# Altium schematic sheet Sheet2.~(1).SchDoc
size A3
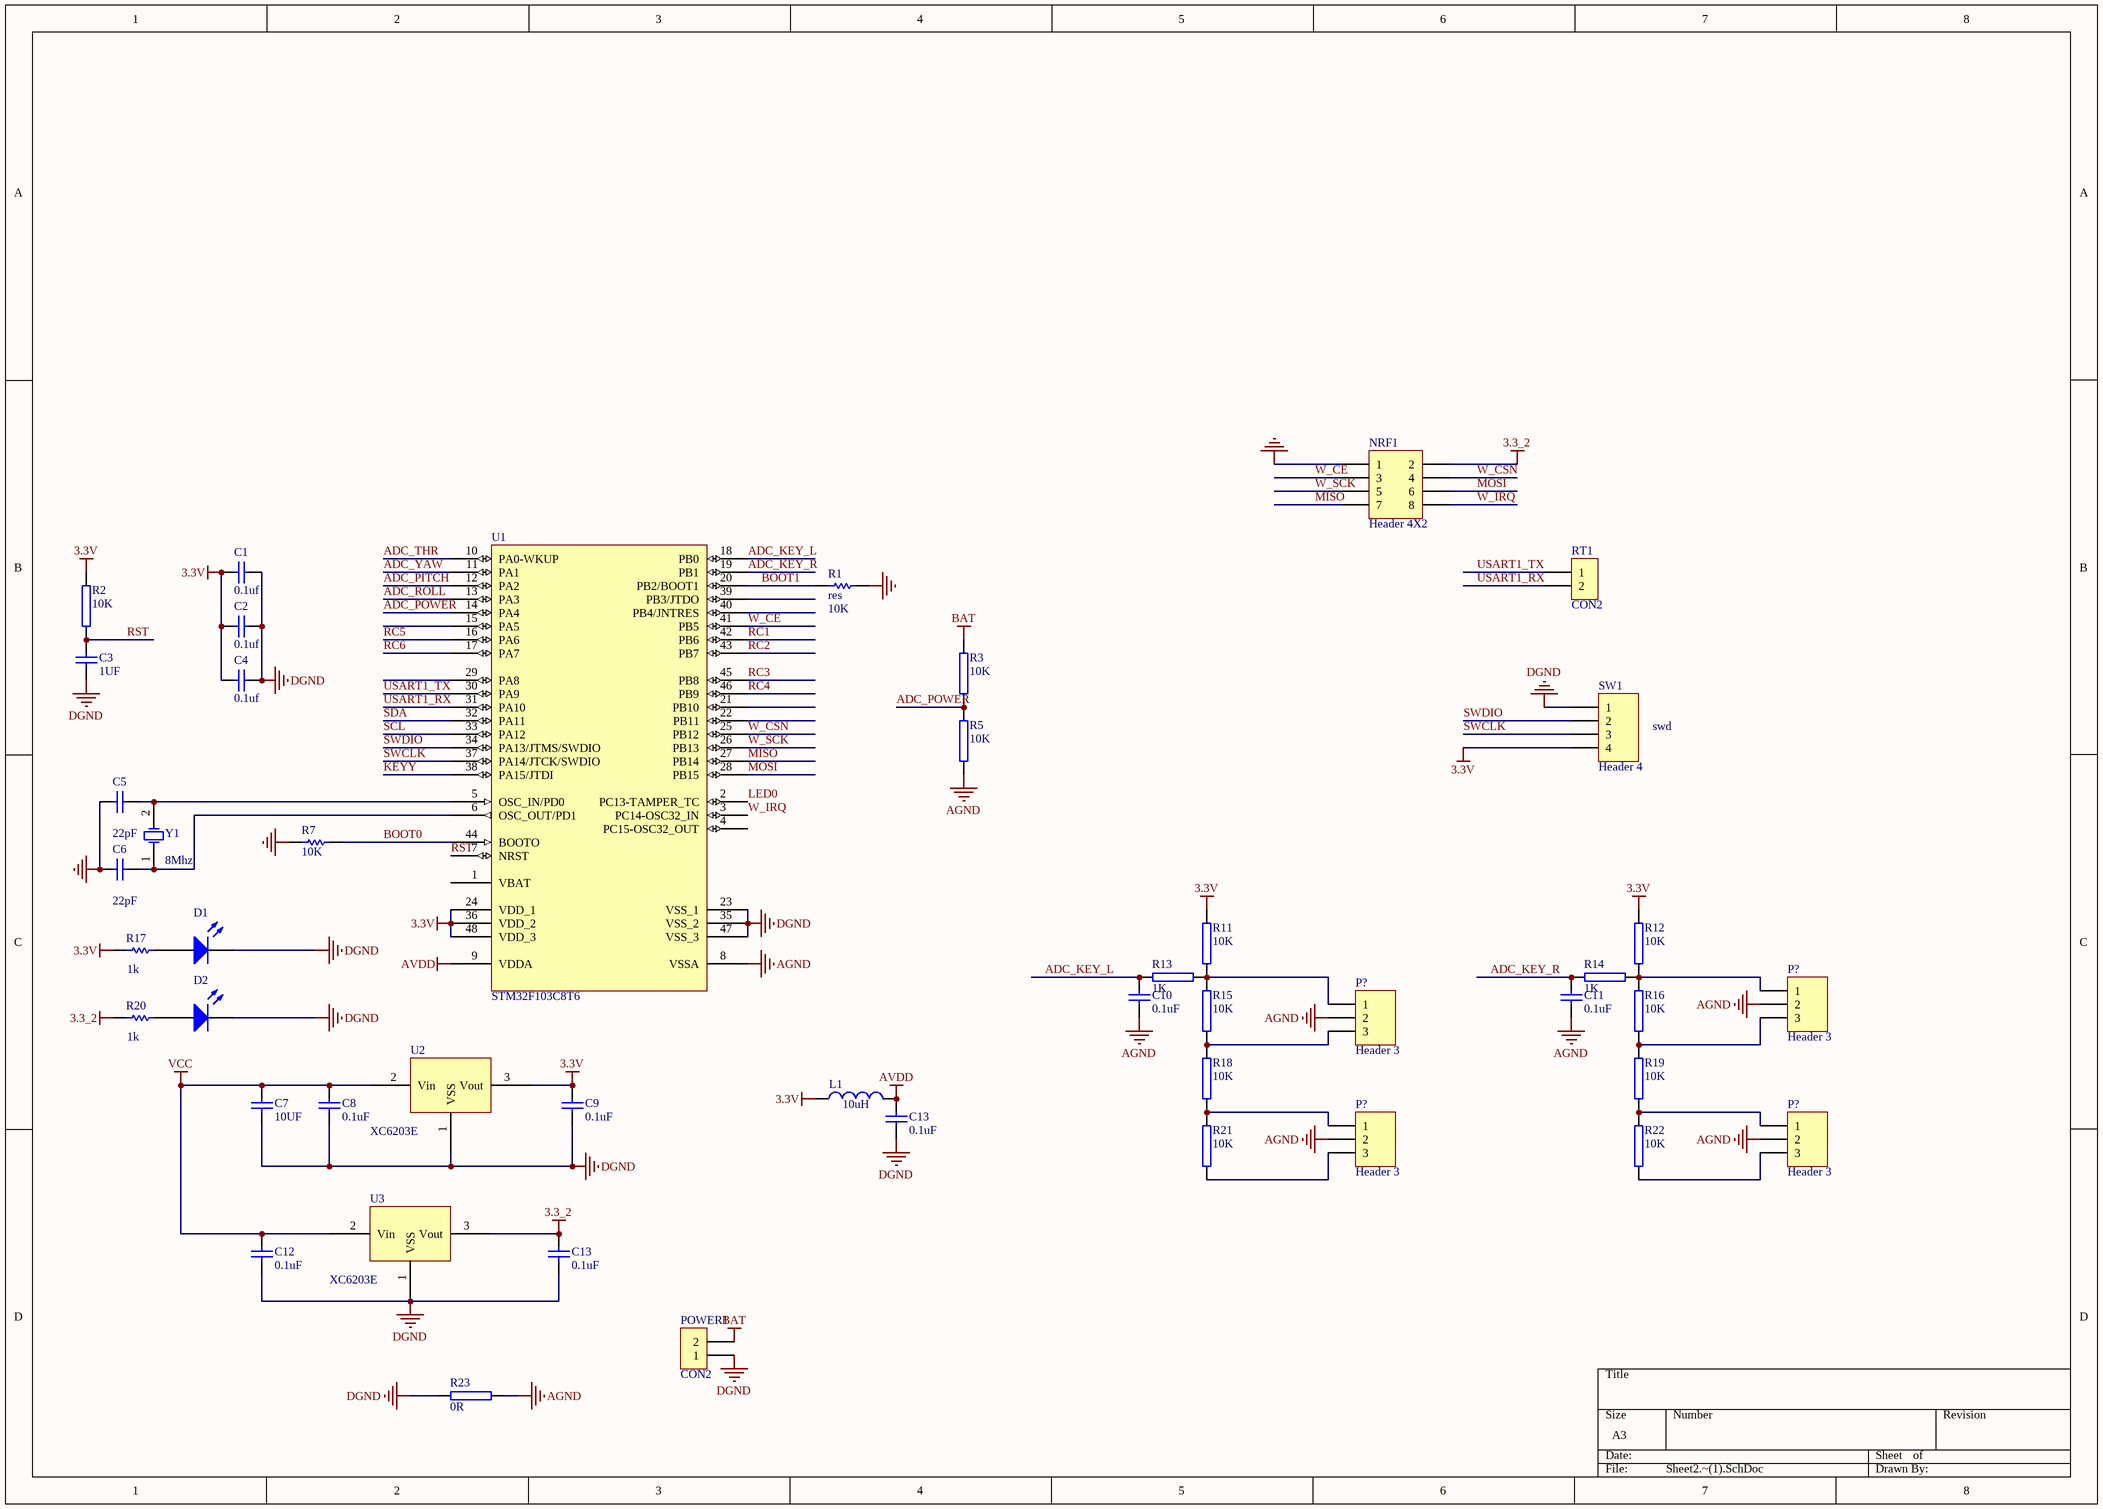
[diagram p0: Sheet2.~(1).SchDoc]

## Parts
(Parts that share a designator on the sheet are numbered #1, #2 ... from top to bottom, then left to right.)
C1  value 0.1uf  [0805]  (hidden comment: cap)
C2  value 0.1uf  [0805]  (hidden comment: cap)
C3  value 1UF  [0805]  (hidden comment: cap)
C4  value 0.1uf  [0805]  (hidden comment: cap)
C5  value 22pF  [0805]  (hidden comment: cap)
C6  value 22pF  [0805]  (hidden comment: cap)
C7  value 10UF  [0805]  (hidden comment: cap)
C8  value 0.1uF  [0805]  (hidden comment: cap)
C9  value 0.1uF  [0805]  (hidden comment: cap)
C10  value 0.1uF  [0805]  (hidden comment: cap)
C11  value 0.1uF  [0805]  (hidden comment: cap)
C12  value 0.1uF  [0805]  (hidden comment: cap)
C13#1  value 0.1uF  [0805]  (hidden comment: cap)
C13#2  value 0.1uF  [0805]  (hidden comment: cap)
D1  LED0  [0805]  (value not drawn)
D2  LED0  [0805]  (value not drawn)
L1  value 10uH  [0805]  (hidden comment: Inductor)
NRF1  Header 4X2  [HDR2X4]
P?#1  Header 3  [HDR1X3]
P?#2  Header 3  [HDR1X3]
P?#3  Header 3  [HDR1X3]
P?#4  Header 3  [HDR1X3]
POWER1  CON2  [SIP2]
R1  res  res: 10K  [0805]
R2  10K  [0805]
R3  10K  [0805]
R5  10K  [0805]
R7  res: 10K  [0805]  (hidden comment: res)
R11  10K  [0805]
R12  10K  [0805]
R13  1K  [0805]
R14  1K  [0805]
R15  10K  [0805]
R16  10K  [0805]
R17  res: 1k  [0805]  (hidden comment: res)
R18  10K  [0805]
R19  10K  [0805]
R20  res: 1k  [0805]  (hidden comment: res)
R21  10K  [0805]
R22  10K  [0805]
R23  0R  [0805]
RT1  CON2  [SIP2]
SW1  Header 4  [HDR1X4]
U1  STM32F103C8T6  [LQFP48S]
U2  XC6203E  [SOT-89]
U3  XC6203E  [SOT-89]
Y1  5032xtal  [XTAL]  (value not drawn)

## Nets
3.3_2: C13#2.2 NRF1.2 R20.1 U3.3(Vout)
3.3V: C1.2 C2.2 C4.2 C9.2 L1.1 R2.2 R11.2 R12.2 R17.1 SW1.4 U1.24(VDD_1) U1.36(VDD_2) U1.48(VDD_3) U2.3(Vout)
AGND: C10.1 C11.1 P?#1.2 P?#2.2 P?#3.2 P?#4.2 R5.1 R23.2 U1.8(VSSA)
AVDD: C13#1.2 L1.2 U1.9(VDDA)
BAT: POWER1.2 R3.2
DGND: C1.1 C2.1 C3.1 C4.1 C7.1 C8.1 C9.1 C12.1 C13#1.1 C13#2.1 D1.2(K) D2.2(K) POWER1.1 R23.1 SW1.1 U1.23(VSS_1) U1.35(VSS_2) U1.47(VSS_3) U2.1(VSS) U3.1(VSS)
GND: C5.1 C6.1 NRF1.1 R1.2 R7.1
VCC: C7.2 C8.2 C12.2 U2.2(Vin) U3.2(Vin)
ADC_KEY_L: C10.2 R13.2 U1.18(PB0)
ADC_KEY_R: C11.2 R14.2 U1.19(PB1)
ADC_PITCH: U1.12(PA2)
ADC_POWER: R3.1 R5.2 U1.14(PA4)
ADC_ROLL: U1.13(PA3)
ADC_THR: U1.10(PA0-WKUP)
ADC_YAW: U1.11(PA1)
BOOT0: R7.2 U1.44(BOOTO)
BOOT1: R1.1 U1.20(PB2/BOOT1)
KEYY: U1.38(PA15/JTDI)
LED0: U1.2(PC13-TAMPER_TC)
MISO: NRF1.7 U1.27(PB14)
MOSI: NRF1.6 U1.28(PB15)
RC1: U1.42(PB6)
RC2: U1.43(PB7)
RC3: U1.45(PB8)
RC4: U1.46(PB9)
RC5: U1.16(PA6)
RC6: U1.17(PA7)
RST: C3.2 R2.1 U1.7(NRST)
SCL: U1.33(PA12)
SDA: U1.32(PA11)
SWCLK: SW1.3 U1.37(PA14/JTCK/SWDIO)
SWDIO: SW1.2 U1.34(PA13/JTMS/SWDIO)
USART1_RX: RT1.2 U1.31(PA10)
USART1_TX: RT1.1 U1.30(PA9)
W_CE: NRF1.3 U1.41(PB5)
W_CSN: NRF1.4 U1.25(PB12)
W_IRQ: NRF1.8 U1.3(PC14-OSC32_IN)
W_SCK: NRF1.5 U1.26(PB13)
NetC5_2: C5.2 U1.5(OSC_IN/PD0) Y1.2(OSC2)
NetC6_2: C6.2 U1.6(OSC_OUT/PD1) Y1.1(OSC1)
NetD1_1: D1.1(A) R17.2
NetD2_1: D2.1(A) R20.2
NetP?#1_1: P?#1.1 R12.1 R14.1 R16.2
NetP?#1_3: P?#1.3 R16.1 R19.2
NetP?#2_1: P?#2.1 R11.1 R13.1 R15.2
NetP?#2_3: P?#2.3 R15.1 R18.2
NetP?#3_1: P?#3.1 R18.1 R21.2
NetP?#3_3: P?#3.3 R21.1
NetP?#4_1: P?#4.1 R19.1 R22.2
NetP?#4_3: P?#4.3 R22.1

Not connected (* = marked no-connect by the designer): U1 1(VBAT) 4(PC15-OSC32_OUT) 15(PA5) 21(PB10) 22(PB11) 29(PA8) 39(PB3/JTDO) 40(PB4/JNTRES)

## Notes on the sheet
- swd

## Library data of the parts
D1 D2 = LED0: Typical INFRARED GaAs LED
NRF1 = Header 4X2: Header, 4-Pin, Dual row
P?#1-P?#4 = Header 3: Header, 3-Pin
R2 R3 R5 R11-R16 R18 R19 R21-R23 = RES
SW1 = Header 4: Header, 4-Pin
U2 U3 = XC6203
